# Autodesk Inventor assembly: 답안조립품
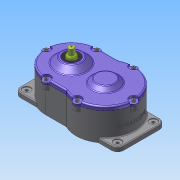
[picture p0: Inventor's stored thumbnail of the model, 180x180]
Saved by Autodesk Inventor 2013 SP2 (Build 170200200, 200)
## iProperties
Created: 2025-09
Part Number: 답안조립품
Document SubType Name: Assembly
Designer: a
Author: a
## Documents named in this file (19)
- C:\Users\a\Desktop\750903V1016\답안조립품.iam
- C:\Users\a\Desktop\750903V1016\본체.ipt
- C:\Users\a\Desktop\750903V1016\스러스트 볼 베어링 51102.ipt
- C:\Users\a\Desktop\750903V1016\깊은 홈 볼 베어링 6904.ipt
- C:\Users\a\Desktop\750903V1016\6각 구멍붙이 볼트 M6x12.ipt
- C:\Users\a\Desktop\750903V1016\슬롯 축.ipt
- C:\Users\a\Desktop\750903V1016\어댑터.ipt
- C:\Users\a\Desktop\750903V1016\슬롯.ipt
- C:\Users\a\Desktop\750903V1016\칼라.ipt
- C:\Users\a\Desktop\750903V1016\평행 키 6x6x14.ipt
- C:\Users\a\Desktop\750903V1016\구동 축.ipt
- C:\Users\a\Desktop\750903V1016\구동 휠.ipt
- C:\Users\a\Desktop\750903V1016\오일 실 20 35 8.ipt
- C:\Users\a\Desktop\750903V1016\스프링 와셔 M3.ipt
- C:\Users\a\Desktop\750903V1016\육각 너트 M3.ipt
- C:\Users\a\Desktop\750903V1016\캠 플로워.ipt
- C:\Users\a\Desktop\750903V1016\평 와셔 M3.ipt
- C:\Users\a\Desktop\750903V1016\6각 구멍붙이 볼트 M4x10.ipt
- C:\Users\a\Desktop\750903V1016\커버.ipt
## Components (9 placed, 4 different names)
1. 6각 구멍붙이 볼트 M6x12:1 — 각도:1
2. 구동 축:1
3. 구동 휠:1
4. 6각 구멍붙이 볼트 M4x10:1 — 각도:8
5. 6각 구멍붙이 볼트 M4x10:2 — 각도:7
6. 6각 구멍붙이 볼트 M4x10:3 — 각도:6
7. 6각 구멍붙이 볼트 M4x10:4 — 각도:9
8. 6각 구멍붙이 볼트 M4x10:5 — 각도:5
9. 6각 구멍붙이 볼트 M4x10:6 — 각도:4
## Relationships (7: Angle 7)
- 각도:1 [Angle]: 6각 구멍붙이 볼트 M6x12:1
- 각도:4 [Angle]: 6각 구멍붙이 볼트 M4x10:6
- 각도:5 [Angle]: 6각 구멍붙이 볼트 M4x10:5
- 각도:6 [Angle]: 6각 구멍붙이 볼트 M4x10:3
- 각도:7 [Angle]: 6각 구멍붙이 볼트 M4x10:2
- 각도:8 [Angle]: 6각 구멍붙이 볼트 M4x10:1
- 각도:9 [Angle]: 6각 구멍붙이 볼트 M4x10:4
